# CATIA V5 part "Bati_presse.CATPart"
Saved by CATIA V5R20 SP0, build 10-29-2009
Part number: Bati_presse
Bounding box of the stored display mesh (mm): x -20 to 20, y -10.906 to 85.919, z -2.273 to 56.5
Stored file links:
  C:\Users\J\IAO_2012_jgossard\Bati_presse.CATPart
  C:\Users\J\IAO_2012_jgossard\jgossard.CATProduct
  C:\Users\J\TP thinkmotion IAO\Bielle_5.CATPart
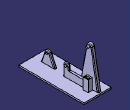
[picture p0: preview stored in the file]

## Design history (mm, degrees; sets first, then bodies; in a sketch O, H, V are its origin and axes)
Set1
  Plane1 "Plan_ref": linked copy from another document
  Line1 "Corps_bati": linked copy from another document
  Point1 "Point_A": linked copy from another document
  Point2 "Point_G": linked copy from another document
  Point3 "Point_fin_bascule_2": linked copy from another document
  Point4 "Point_D": linked copy from another document
  Line2 "raccord_bati_point_D": linked copy from another document
  Line3 "Axe_pivot_bascule_4_point_E": linked copy from another document
Body1 (main body)
  Sketch1 on Plane1, origin (0, 0, 0), H (0, 1, 0), V (0, 0, 1)
    line L1 (-10.9061, 0) -> (85.9192, 0)
    line L2 (85.9192, 0) -> (85.9192, -2.273)
    line L3 (85.9192, -2.273) -> (-10.9061, -2.273)
    line L4 (-10.9061, -2.273) -> (-10.9061, 0)
    reference projected line E1 (0, 0) -> (80, 0) from Line1
    horizontal: L1 H, L3 H
    vertical: L2 V, L4 V
    coincidence: L1 E1
  Pad1: profile Sketch1, direction (1, 0, 0), length 20, opposite side length 20
  Sketch2 on Plane1, origin (0, 0, 0), H (0, 1, 0), V (0, 0, 1)
    line L1 (0.838, 0) -> (20.8807, 0)
    line L2 (20.8807, 0) -> (13.1703, 16.483)
    line L3 (0.838, 0) -> (6.7096, 16.1931)
    arc A1 centre (10, 15) radius 3.5 from (6.7096, 16.1931) to (13.1703, 16.483) cw
    point P5 (10, 15)
    reference projected point E1 (10, 15) from Point1
    reference projected line E2 (0, 0) -> (80, 0) from Line1
    reference projected line E3 (0, 0) -> (80, 0) from Line1
    radius A1 = 3.5
    angle L2 L3 = 45
    angle E3 L2 = 115.0692
    horizontal: L1 H
    tangency: A1 L3, L2 A1
    coincidence: P5 E1, L1 E2
  Pad2: profile Sketch2, direction (-1, 0, 0), length 3, opposite side length -1
  Sketch3 on Plane1, origin (0, 0, 0), H (0, 1, 0), V (0, 0, 1)
    line L1 (36, 0) -> (43.0181, 0)
    line L2 (36, 0) -> (36, 15)
    arc A1 centre (40, 15) radius 4 from (36, 15) to (44, 15) cw
    point P5 (40, 15)
    reference projected point E1 (40, 15) from Point2
    reference projected line E2 (0, 0) -> (80, 0) from Line1
    line L3 (44, 10) -> (67.3723, 10)
    line L4 (68.6191, 11.2469) -> (68.6191, 16.4853)
    line L5 (76, 16.4853) -> (76, 0)
    point P6 (76, 0)
    line L6 (76, 0) -> (43.0181, 0)
    arc A2 centre (67.3723, 11.2469) radius 1.2469 from (68.6191, 11.2469) to (67.3723, 10) cw
    line L7 (68.6191, 16.4853) -> (76, 16.4853)
    line L8 (44, 15) -> (44, 10)
    radius A1 = 4
    radius A2 = 1.2469
    horizontal: L1 H, L3 H, L6 H, L7 H
    tangency: A1 L2, A2 L4, A2 L3, L8 A1
    coincidence: P5 E1, L1 E2, P6 L1
    vertical: L4 V, L5 V
  Pad3: profile Sketch3, direction (1, 0, 0), length 1, opposite side length 2
  Sketch4 on Plane1, origin (0, 0, 0), H (0, 1, 0), V (0, 0, 1)
    line L1 (56.6811, 0) -> (83.3189, 0)
    line L2 (83.3189, 0) -> (73.9392, 53.1946)
    line L3 (56.6811, 0) -> (66.0608, 53.1946)
    arc A1 centre (70, 52.5) radius 4 from (66.0608, 53.1946) to (73.9392, 53.1946) cw
    point P5 (70, 52.5)
    reference projected point E1 (70, 52.5) from Point4
    reference projected line E2 (0, 0) -> (80, 0) from Line1
    reference projected line E3 (85.9192, 0) -> (-10.9061, 0) from edge [face of Pad1 from Sketch1.L1 | end face of Pad1]
    radius A1 = 4
    angle L2 E3 = 100
    angle L2 L3 = 20
    horizontal: L1 H
    tangency: A1 L3, L2 A1
    coincidence: P5 E1, L1 E2
  Pad4: profile Sketch4, direction (-1, 0, 0), length 8, opposite side length -3
  Sketch5 on end face of Pad3, origin (1, 0, 0), H (0, 1, 0), V (0, 0, 1)
    line L1 (68.6191, 16.4853) -> (76, 16.4853)
    point P1 (76, 0)
    line L2 (76, 0) -> (68.6191, 0)
    reference intersected line E1 (68.6191, 16.4853) -> (76, 16.4853) from face of Pad3 from Sketch3.L7
    line L3 (68.6191, 16.4853) -> (68.6191, 0)
    line L4 (76, 0) -> (76, 16.4853)
    reference projected line E2 (68.6191, 15.4687) -> (68.6191, 11.2469) from edge [face of Pad3 from Sketch3.L4 | end face of Pad3]
    reference projected line E3 (76, 0) -> (76, 15.4687) from edge [face of Pad3 from Sketch3.L5 | end face of Pad3]
    horizontal: L1 H, L2 H
    coincidence: P1 H, L1 E1, L3 E2, L4 E3
    vertical: L3 V, L4 V
  Pad5: profile Sketch5, direction (1, 0, 0), length 3
  Sketch6 on face of Pad5, origin (0, 67, 16.4853), H (0, 1, 0), V (1, 0, 0)
    line L1 (2.6191, 3) -> (8, 3)
    line L2 (8, 3) -> (8, 0)
    line L3 (8, 0) -> (2.6191, 0)
    line L4 (2.6191, 0) -> (2.6191, 3)
    reference projected line E1 (-67, 0) -> (13, 0) from Line1
    reference projected line E2 (1.6191, -2) -> (1.6191, 1) from edge [face of Pad5 | face of Pad5]
    reference projected line E3 (9, -2) -> (9, 1) from edge [face of Pad5 | face of Pad5]
    reference projected line E4 (9, 4) -> (1.6191, 4) from edge [face of Pad5 | end face of Pad5]
    distance L4 E2 = 1
    distance L2 E3 = 1
    distance L1 E4 = 1
    horizontal: L1 H, L3 H
    vertical: L2 V, L4 V
    coincidence: L3 E1
  Pocket1: profile Sketch6, direction (0, 0, -1), length 2
  Sketch7 on start face of Pad4, origin (-3, 0, 0), H (0, 1, 0), V (0, 0, 1)
    circle A1 centre (70, 52.5) radius 1.5
    point P1 (70, 52.5)
    reference projected point E1 (70, 52.5) from Point4
    radius A1 = 1.5
    coincidence: E1 P1
  Pad6: profile Sketch7, direction (1, 0, 0), length 3
  Sketch8 on start face of Pad2, origin (-1, 0, 0), H (0, 1, 0), V (0, 0, 1)
    circle A1 centre (10, 15) radius 1.25
    point P1 (10, 15)
    reference projected point E1 (10, 15) from Point1
    radius A1 = 1.25
    coincidence: P1 E1
  Pad7: profile Sketch8, direction (1, 0, 0), length 1
  Sketch9 on end face of Pad3, origin (1, 0, 0), H (0, 1, 0), V (0, 0, 1)
    circle A1 centre (40, 15) radius 1.5
    point P1 (40, 15)
    reference projected point E1 (40, 15) from Point2
    radius A1 = 1.5
    coincidence: P1 E1
  Pad8: profile Sketch9, direction (1, 0, 0), length 1
  Sketch10 on end face of Pad2, origin (-3, 0, 0), H (0, -1, 0), V (0, 0, 1)
    line L1 (-20.8807, 0) -> (-0.838, 0)
    line L2 (-0.838, 0) -> (-6.7096, 16.1931)
    line L3 (-20.8807, 0) -> (-13.1703, 16.483)
    arc A1 centre (-10, 15) radius 3.5 from (-13.1703, 16.483) to (-6.7096, 16.1931) cw
    reference intersected line E1 (-85.9192, 0) -> (10.9061, 0) from face of Pad1 from Sketch1.L1
    reference projected line E2 (-6.7096, 16.1931) -> (-0.838, 0) from edge [end face of Pad2 | face of Pad2 from Sketch2.L3]
    reference projected line E3 (-20.8807, 0) -> (-13.1703, 16.483) from edge [end face of Pad2 | face of Pad2 from Sketch2.L2]
    reference projected point E4 (-10, 15) from axis of face of Pad2 from Sketch2.A1
    horizontal: L1 H
    tangency: A1 L2, A1 L3
    coincidence: L1 E1, L2 E2, L3 E3
    concentricity: A1 E4
  Pad9: profile Sketch10, direction (-1, 0, 0), length 2
  Fillet1: radius 1, on face of Pad4 from Sketch4.L2; face of Pad3 from Sketch3.L8; face of Pad9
